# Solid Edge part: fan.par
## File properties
Author: edge
Template: NORMAL.PAR
Last saved by: edge
Revision: 60
Application: Solid Edge
Accuracy: 0.99
非切断部品: False
文書内容のタイプ: 0
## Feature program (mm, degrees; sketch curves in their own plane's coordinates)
sketch for "ExtrudedProtrusion_1" plane through (0, 0, 0) normal (1, 0, 0) x-axis (0, 1, 0)
  circle centre (0, 0) radius 50
extrude "ExtrudedProtrusion_1" add finite 25 along -normal
sketch for "unnamed Protrusion 1" plane through (0, 0, 0) normal (1, 0, 0) x-axis (0, 1, 0)
  circle centre (0, 0) radius 62.5
extrude "unnamed Protrusion 1" add finite 10 along +normal
sketch for "Hole_1" plane through (0, 0, 0) normal (1, 0, 0) x-axis (0, 1, 0)
  hole centre (0, 0) bore radius 45
hole "Hole_1" through
sketch for "unnamed Protrusion 2" plane through (0, 0, 0) normal (1, 0, 0) x-axis (0, 1, 0)
  line (61.8718, -44.1942) -> (52.1401, -34.4624)
  arc centre (53.033, -53.033) radius 12.5 from (61.8718, -44.1942) to (44.1942, -61.8718) cw
  line (44.1942, -61.8718) -> (34.4624, -52.1401)
extrude "unnamed Protrusion 2" add to key point along +normal
pattern "unnamed Pattern 1" of "unnamed Protrusion 2"
pattern "unnamed Pattern 2"
sketch for "Hole_2" plane through (0, 0, 0) normal (1, 0, 0) x-axis (0, 1, 0)
  hole centre (-53.033, 53.033) bore radius 6
hole "Hole_2" through  CounterBoreDepth = 5 mm
pattern "unnamed Pattern 3" of "Hole_2"
hole "unnamed Hole 1" through
hole "unnamed Hole 2" through
hole "unnamed Hole 3" through
sketch for "unnamed Protrusion 3" plane through (0, 0, 0) normal (1, 0, 0) x-axis (0, 1, 0)
  line (3, 45) -> (3, 0)
  line (-3, 0) -> (3, 0)
  line (-3, 45) -> (-3, 0)
  arc centre (0, 0) radius 45.0999 from (-3, 45) to (3, 45) cw
  dimension (linear) = 3
  dimension (linear) = 3
extrude "unnamed Protrusion 3" add along +normal
pattern "unnamed Pattern 4" of "unnamed Protrusion 3"
extrude "unnamed Protrusion 4" add
extrude "unnamed Protrusion 5" add
extrude "unnamed Protrusion 6" add
extrude "unnamed Protrusion 7" add
extrude "unnamed Protrusion 8" add
extrude "unnamed Protrusion 9" add
extrude "unnamed Protrusion 10" add
fillet "Round_1" radius 10
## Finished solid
Body 1: solid body, 58 faces, 163 edges, 96 vertices.
  Faces by surface: plane 32, cylinder 26
  Edges by curve: line 96, circle 67
Bounding box of the edges (mm): 35.000 x 131.066 x 131.066, from (-25, -65.533, -65.533) to (10, 65.533, 65.533).
Cylindrical faces by radius (mm): R6 x4, R7 x4, R10 x8, R12.5 x4, R45 x1, R50 x1, R62.5 x4
Planar faces by outward normal: +x 2, +y 2, +z 2, -x 6, -y 2, -z 2, oblique 16
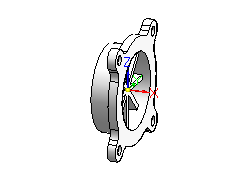
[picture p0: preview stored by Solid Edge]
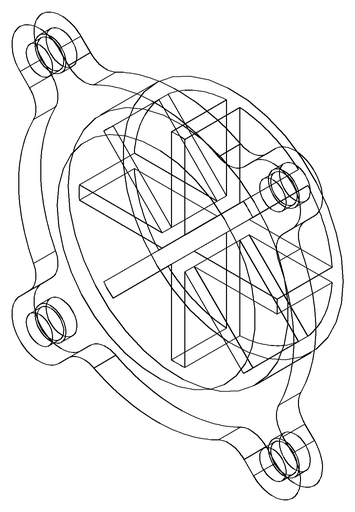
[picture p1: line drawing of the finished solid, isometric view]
